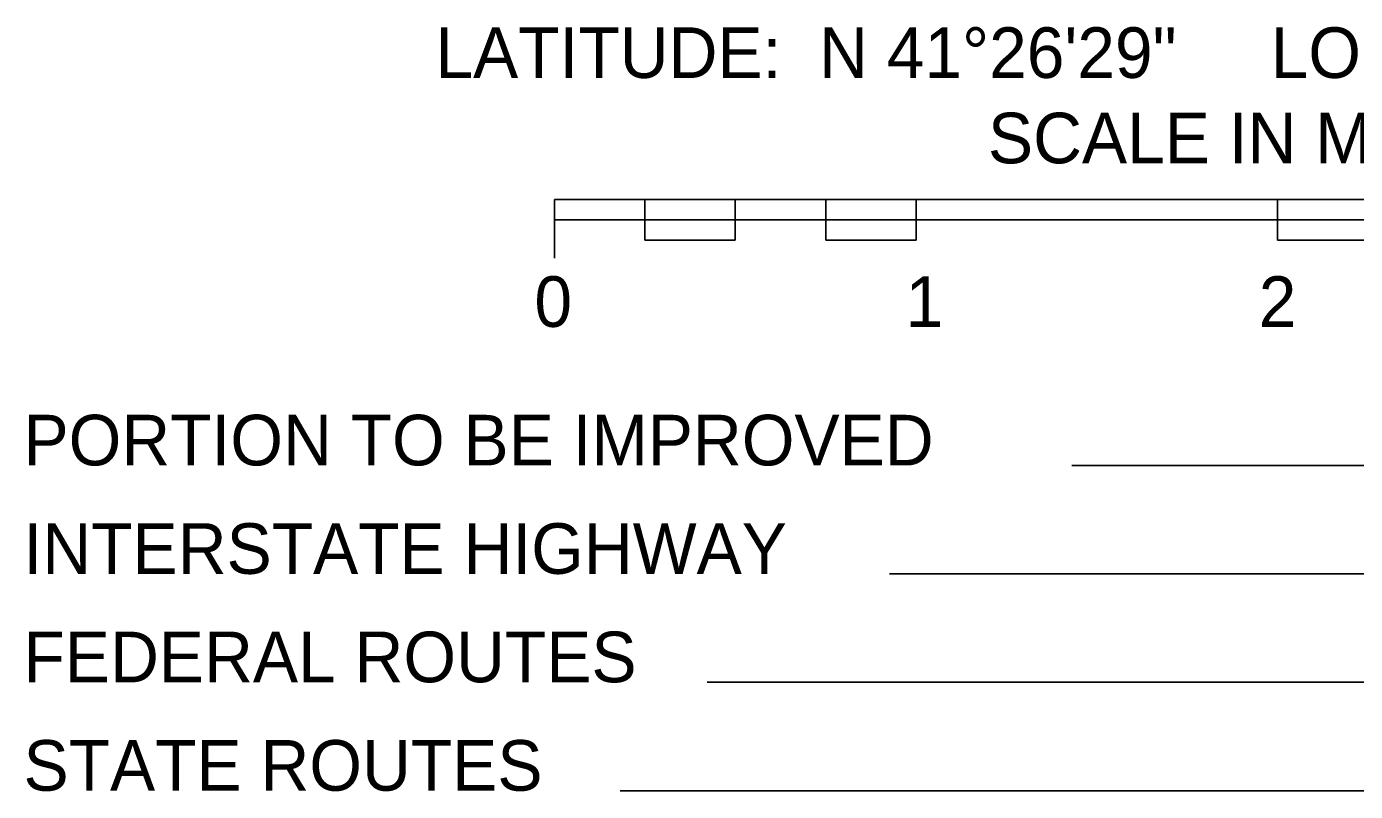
# Model space of a CAD drawing. Extents: x 0 to 34, y 0 to 22.
# Drawn here: x 1.94 to 5.615, y 11.222 to 13.338 of the extents above; entities that cross this region are included whole.
import ezdxf

# ---------------------------------------------------------------- set-up
doc = ezdxf.new("R2010")
doc.units = 0
doc.layers.add('SH_Data', color=7, linetype='Continuous')
doc.layers.add('SH_Text', color=7, linetype='Continuous')

msp = doc.modelspace()

# ---------------------------------------------------------------- linework, layer by layer
at = {"layer": 'SH_Data'}
for p, q in [((3.4004, 12.8596), (3.4004, 12.6971)), ((3.4004, 12.8596), (7.4004, 12.8596)), ((3.6504, 12.7471), (3.6504, 12.8596)), ((3.9004, 12.7471), (3.9004, 12.8596)), ((4.1504, 12.8596), (4.1504, 12.7471)), ((4.4004, 12.7471), (4.4004, 12.8596)), ((5.4004, 12.8596), (5.4004, 12.7471)), ((3.4004, 12.8033), (3.6504, 12.8033)), ((3.6504, 12.8033), (3.9004, 12.8033)), ((3.9004, 12.8033), (3.6504, 12.8033)), ((3.6504, 12.8033), (3.6504, 12.7471)), ((4.1504, 12.8033), (3.9004, 12.8033)), ((3.9004, 12.7471), (3.9004, 12.8033)), ((4.4004, 12.8033), (4.1504, 12.8033)), ((4.4004, 12.8033), (4.1504, 12.8033)), ((4.1504, 12.8033), (4.1504, 12.7471)), ((5.4004, 12.8033), (4.4004, 12.8033)), ((4.4004, 12.7471), (4.4004, 12.8033)), ((6.4004, 12.8033), (5.4004, 12.8033)), ((6.4004, 12.8033), (5.4004, 12.8033)), ((5.4004, 12.8033), (5.4004, 12.7471)), ((3.6504, 12.7471), (3.9004, 12.7471)), ((4.1504, 12.7471), (4.4004, 12.7471)), ((5.4004, 12.7471), (6.4004, 12.7471)), ((8.037, 12.1238), (4.8309, 12.1238)), ((7.6373, 11.8238), (4.3268, 11.8238)), ((7.6373, 11.5238), (3.8226, 11.5238)), ((7.6373, 11.2238), (3.582, 11.2238))]:
    msp.add_line(p, q, dxfattribs=at)
for points in [[(3.4004, 12.8596), (3.4004, 12.8033), (3.6504, 12.8033), (3.6504, 12.8596)], [(3.9004, 12.8596), (3.9004, 12.8033), (4.1504, 12.8033), (4.1504, 12.8596)], [(4.4004, 12.8596), (4.4004, 12.8033), (5.4004, 12.8033), (5.4004, 12.8596)]]:
    msp.add_lwpolyline(points, close=True, dxfattribs=at)

# ---------------------------------------------------------------- texts
for s, p in [('SCALE IN MILES', (4.5991, 12.9596)), ('0', (3.3448, 12.5071)), ('1', (4.3713, 12.5071)), ('2', (5.3481, 12.5071))]:
    msp.add_text(s, height=0.14, dxfattribs=at).set_placement(p)
at = {"layer": 'SH_Text'}
for s, p in [('LATITUDE:  N 41°26\'29"     LONGITUDE:  W 84°35\'44"', (3.071, 13.1958)), ('PORTION TO BE IMPROVED', (1.9317, 12.1238)), ('INTERSTATE HIGHWAY', (1.9317, 11.8238)), ('FEDERAL ROUTES', (1.9317, 11.5238)), ('STATE ROUTES', (1.9317, 11.2238))]:
    msp.add_text(s, height=0.14, dxfattribs=at).set_placement(p)

doc.saveas('drawing.dxf')
